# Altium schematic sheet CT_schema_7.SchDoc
size 274 x 160 mm
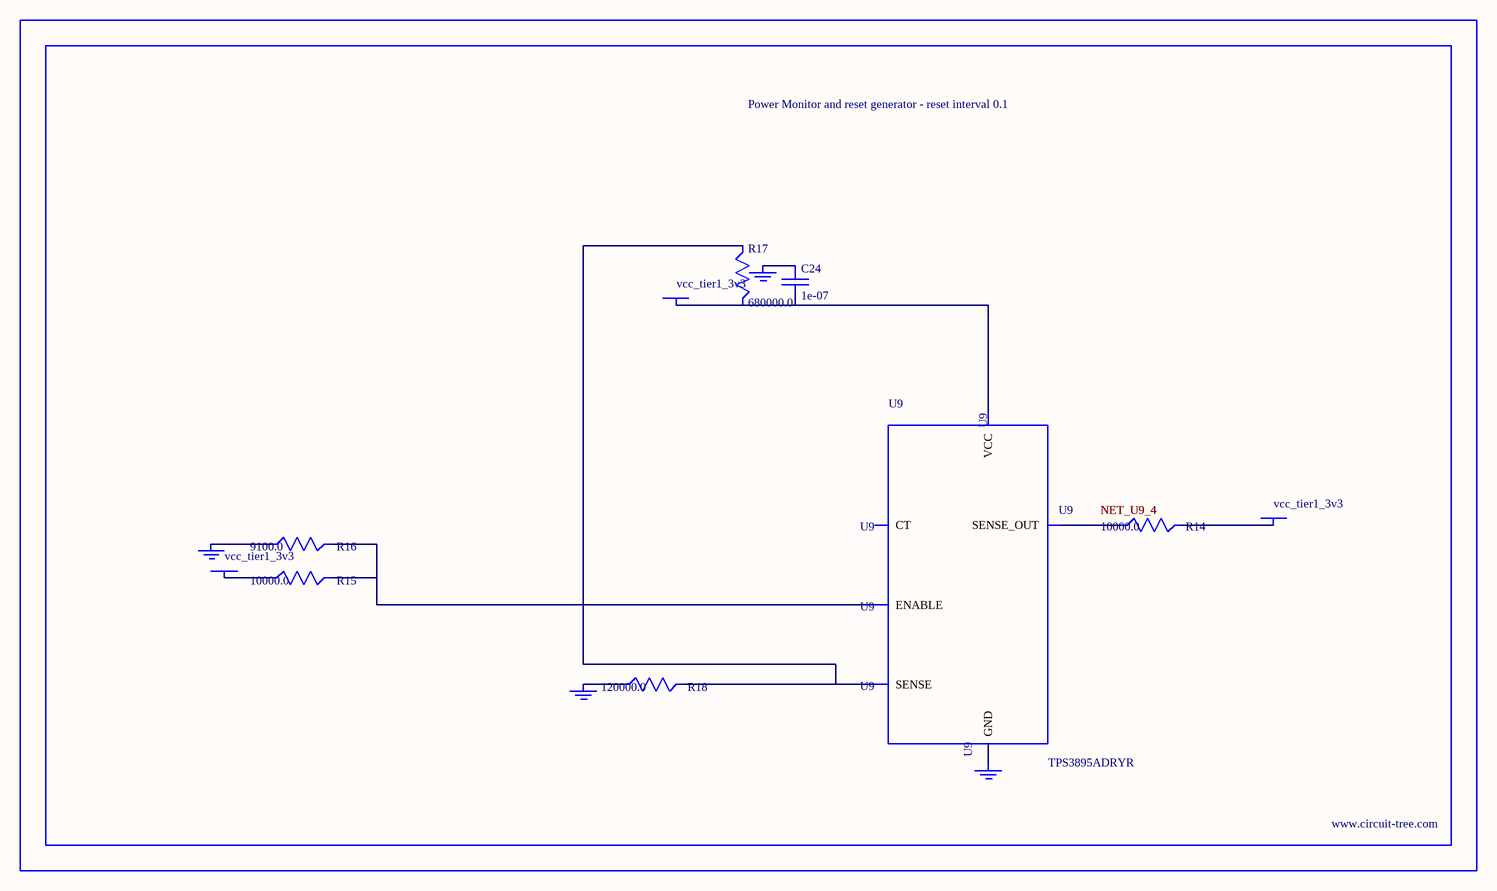
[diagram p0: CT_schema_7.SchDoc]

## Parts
BORDER6  (no value)
C24  1e-07  [C0402]
GND_INSTANCE_6_0  (no value)
GND_INSTANCE_6_1  (no value)
GND_INSTANCE_6_2  (no value)
GND_INSTANCE_6_3  (no value)
POWER_INSTANCE_6_0  vcc_tier1_3v3
POWER_INSTANCE_6_1  vcc_tier1_3v3
POWER_INSTANCE_6_2  vcc_tier1_3v3
R14  10000.0  [R0603]
R15  10000.0  [R0603]
R16  9100.0  [R0603]
R17  680000.0  [R0603]
R18  120000.0  [R0603]
U9  TPS3895ADRYR  [SON-6]

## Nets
NetC24_1: C24.1 GND_INSTANCE_6_2.0(GND)
NetC24_2: C24.2 POWER_INSTANCE_6_2.0(PWR) R17.2 U9.6(VCC)
NetGND_INSTANCE_6_0_0: GND_INSTANCE_6_0.0(GND) R16.1
NetGND_INSTANCE_6_1_0: GND_INSTANCE_6_1.0(GND) R18.1
NetGND_INSTANCE_6_3_0: GND_INSTANCE_6_3.0(GND) U9.2(GND)
NetPOWER_INSTANCE_6_0_0: POWER_INSTANCE_6_0.0(PWR) R15.1
NetPOWER_INSTANCE_6_1_0: POWER_INSTANCE_6_1.0(PWR) R14.2
NetR14_1: R14.1 U9.4(SENSE_OUT)
NetR15_2: R15.2 R16.2 U9.1(ENABLE)
NetR17_1: R17.1 R18.2 U9.3(SENSE)

Not connected (* = marked no-connect by the designer): U9 5(CT)

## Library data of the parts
BORDER6 = BORDER_PAGE6
C24 = C0402C104K3RACTU
GND_INSTANCE_6_0-GND_INSTANCE_6_3 = GND
POWER_INSTANCE_6_0-POWER_INSTANCE_6_2 = PWR
R14 R15 = RC0603JR-0710KL
R16 = RC0603JR-079K1L
R17 = RC0603JR-07680KL
R18 = RC0603JR-07120KL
